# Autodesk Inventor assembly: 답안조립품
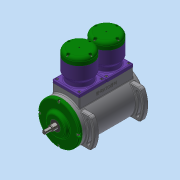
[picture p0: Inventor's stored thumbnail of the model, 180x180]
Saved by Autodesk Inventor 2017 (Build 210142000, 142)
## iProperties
Part Number: 답안조립품
Material: 일반
Document SubType Name: Assembly
Designer: Administrator
Author: Administrator
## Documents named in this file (16)
- C:\Users\Administrator\Desktop\620106V1001\답안조립품.iam
- C:\Users\Administrator\Desktop\620106V1001\너트 M4.ipt
- C:\Users\Administrator\Desktop\620106V1001\베어링 6303.ipt
- C:\Users\Administrator\Desktop\620106V1001\본체.ipt
- C:\Users\Administrator\Desktop\620106V1001\볼트 M4 x 12.ipt
- C:\Users\Administrator\Desktop\620106V1001\볼트 M5 x 20.ipt
- C:\Users\Administrator\Desktop\620106V1001\실린더.ipt
- C:\Users\Administrator\Desktop\620106V1001\실린더헤드.ipt
- C:\Users\Administrator\Desktop\620106V1001\앞커버.ipt
- C:\Users\Administrator\Desktop\620106V1001\오일 실 17 x 32 x 8.ipt
- C:\Users\Administrator\Desktop\620106V1001\육각 머리 볼트 M4 x 16.ipt
- C:\Users\Administrator\Desktop\620106V1001\커넥팅로드 엔드.ipt
- C:\Users\Administrator\Desktop\620106V1001\커넥팅로드.ipt
- C:\Users\Administrator\Desktop\620106V1001\크랭크축.ipt
- C:\Users\Administrator\Desktop\620106V1001\피스톤.ipt
- C:\Users\Administrator\Desktop\620106V1001\피스톤핀.ipt
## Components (4 placed, 2 different names)
1. 피스톤:1
2. 피스톤핀:1
3. 피스톤:2
4. 피스톤핀:2
